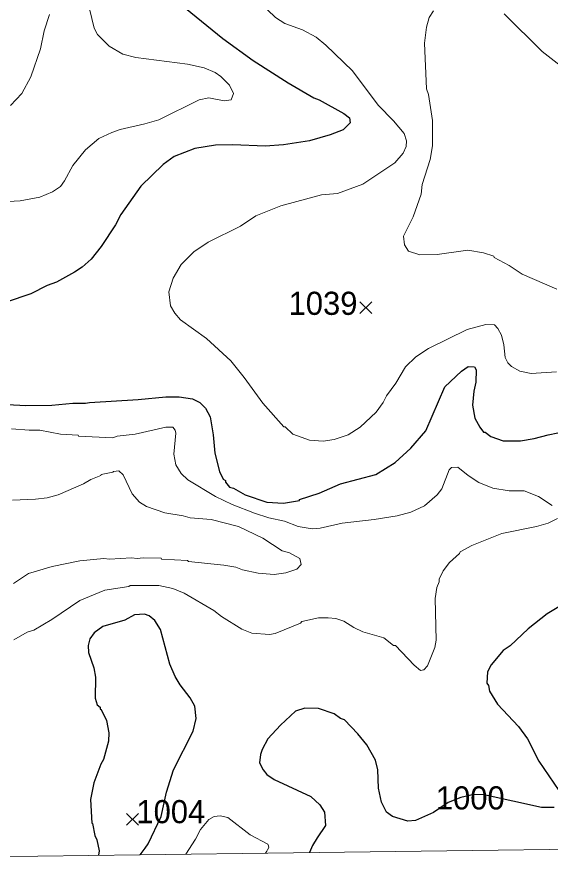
# Model space of a CAD drawing. Extents: x 265.7 to 292.1, y 7676.2 to 7704.2.
# Drawn here: x 285.312 to 287.156, y 7676.365 to 7679.337 of the extents above; entities that cross this region are included whole.
import ezdxf
from ezdxf.enums import TextEntityAlignment as Align

# ---------------------------------------------------------------- set-up
doc = ezdxf.new("R2010")
doc.units = 0
doc.header["$LTSCALE"] = 0.032
for name, color, linetype, lineweight in [('1', 7, 'Continuous', 25), ('2', 7, 'Continuous', 13), ('21', 7, 'Continuous', 25), ('63', 7, 'Continuous', 25)]:
    doc.layers.add(name, color=color, linetype=linetype, lineweight=lineweight)
doc.layers.add('61', color=7, linetype='Continuous')

msp = doc.modelspace()

# ---------------------------------------------------------------- linework, layer by layer
at = {"layer": '1'}
for points in [[(285.8746, 7679.3833), (286.0222, 7679.2636), (286.1267, 7679.1878), (286.248, 7679.1104), (286.3366, 7679.0585), (286.355, 7679.0513), (286.4411, 7679.0042), (286.4603, 7678.9891), (286.4627, 7678.9715), (286.4387, 7678.9476), (286.3933, 7678.93), (286.3214, 7678.9093), (286.2321, 7678.8957), (286.1682, 7678.8909), (286.0565, 7678.8957), (285.9975, 7678.8949), (285.9257, 7678.883), (285.8538, 7678.855), (285.8163, 7678.8279), (285.7389, 7678.7529), (285.6703, 7678.6548), (285.6511, 7678.6196), (285.6017, 7678.5438), (285.5674, 7678.4999), (285.5362, 7678.4728), (285.5099, 7678.4552), (285.4469, 7678.4209), (285.415, 7678.409), (285.3591, 7678.381), (285.2729, 7678.3523)], [(285.8251, 7678.0244), (285.8714, 7678.0244), (285.9177, 7678.0172), (285.9432, 7678.0052), (285.9624, 7677.9853), (285.9783, 7677.9557), (285.9887, 7677.8935), (285.9943, 7677.8297), (286.011, 7677.7658), (286.0238, 7677.7395), (286.031, 7677.7347), (286.031, 7677.7299), (286.0454, 7677.7123), (286.0597, 7677.7084), (286.0996, 7677.6852), (286.1746, 7677.6597), (286.2321, 7677.6565), (286.2879, 7677.6661), (286.2879, 7677.6693), (286.355, 7677.6916), (286.4292, 7677.7235), (286.5513, 7677.7554), (286.6183, 7677.7969), (286.6725, 7677.8472), (286.7236, 7677.9071), (286.7898, 7678.0595), (286.8473, 7678.1129), (286.8704, 7678.1289), (286.892, 7678.1281), (286.8976, 7678.1177), (286.8968, 7678.0754), (286.8896, 7678.0435), (286.8848, 7677.9956), (286.8936, 7677.951), (286.9103, 7677.919), (286.9231, 7677.9023), (286.9287, 7677.9023), (286.9486, 7677.8871), (286.9917, 7677.8719), (287.0508, 7677.8727), (287.0987, 7677.8799), (287.1465, 7677.8935), (287.2471, 7677.9142)], [(285.3415, 7677.9948), (285.4309, 7677.9956), (285.5043, 7678.002), (285.5474, 7678.002), (285.5618, 7678.0052), (285.7294, 7678.0148), (285.8251, 7678.0244)], [(285.2346, 7678.0004), (285.3415, 7677.9948)], [(287.2567, 7677.3421), (287.1433, 7677.2743), (287.0779, 7677.2224), (287.0149, 7677.1634), (286.9917, 7677.1474), (286.9494, 7677.0979), (286.9375, 7677.0732), (286.9351, 7677.0349), (286.9406, 7677.0261), (286.9446, 7677.007), (286.9718, 7676.9615), (287.0444, 7676.8849), (287.0755, 7676.8418), (287.1146, 7676.7652), (287.184, 7676.663)], [(285.7368, 7676.441), (285.7541, 7676.4638), (285.7644, 7676.4793), (285.8092, 7676.5737), (285.8275, 7676.6574), (285.8522, 7676.7349), (285.9201, 7676.8689), (285.9296, 7676.912), (285.9256, 7676.9551), (285.9097, 7676.9838), (285.8754, 7677.0285), (285.8578, 7677.0572), (285.8395, 7677.1003), (285.8067, 7677.22), (285.7868, 7677.2511), (285.7676, 7677.2671), (285.7517, 7677.2735), (285.7166, 7677.2711), (285.6831, 7677.2527), (285.6081, 7677.2304), (285.5777, 7677.2088), (285.5626, 7677.1881), (285.557, 7677.1642), (285.5578, 7677.1402), (285.5769, 7677.0876), (285.5825, 7677.0556), (285.5809, 7676.9822), (285.5881, 7676.9599), (285.5985, 7676.9511), (285.5985, 7676.9447), (285.6017, 7676.9431), (285.62, 7676.9056), (285.6288, 7676.8625), (285.6272, 7676.8338), (285.6097, 7676.77), (285.6009, 7676.754), (285.5769, 7676.6902), (285.565, 7676.6327), (285.569, 7676.5505), (285.5714, 7676.5497), (285.5801, 7676.5082), (285.5873, 7676.4923), (285.5953, 7676.4548), (285.5923, 7676.4394)], [(286.588, 7676.5888), (286.5712, 7676.6231), (286.5608, 7676.671), (286.5576, 7676.7349), (286.5497, 7676.7684), (286.5201, 7676.821), (286.489, 7676.8593), (286.4427, 7676.908), (286.4292, 7676.9128), (286.4068, 7676.928), (286.3534, 7676.9463), (286.3055, 7676.9479), (286.2736, 7676.9375), (286.2217, 7676.8889), (286.1778, 7676.8418), (286.1578, 7676.8051), (286.1523, 7676.7875), (286.1491, 7676.7588), (286.1618, 7676.7349), (286.1746, 7676.7189), (286.1994, 7676.7013), (286.3262, 7676.6423), (286.3581, 7676.6136), (286.3733, 7676.5888), (286.3773, 7676.5425), (286.3486, 7676.4992), (286.3318, 7676.4733), (286.3219, 7676.4485)], [(286.845, 7676.6386), (286.8017, 7676.6216), (286.7508, 7676.5877), (286.6877, 7676.5601), (286.6614, 7676.5577), (286.6087, 7676.5729), (286.588, 7676.5888)], [(287.1673, 7676.604), (287.1242, 7676.6048), (286.9261, 7676.648), (286.8903, 7676.6499), (286.845, 7676.6386)]]:
    msp.add_lwpolyline(points, dxfattribs=at)
at = {"layer": '2'}
for points in [[(285.553, 7679.4001), (285.5777, 7679.2995), (285.5889, 7679.2772), (285.6296, 7679.2373)], [(286.5768, 7678.0052), (286.5521, 7677.9717), (286.497, 7677.919), (286.4555, 7677.8927), (286.4076, 7677.8767), (286.3693, 7677.8711), (286.3214, 7677.8751), (286.264, 7677.8951), (286.2377, 7677.9206), (286.2337, 7677.9206), (286.1602, 7678.002), (286.0964, 7678.0914), (286.0501, 7678.1488), (285.9655, 7678.2262), (285.8762, 7678.2901), (285.8562, 7678.3132), (285.8411, 7678.3396), (285.8355, 7678.3874), (285.8506, 7678.4345), (285.8778, 7678.4824), (285.9217, 7678.5263), (285.9719, 7678.559), (286.0837, 7678.6141), (286.1363, 7678.65), (286.2225, 7678.6851), (286.3629, 7678.7226), (286.4188, 7678.7274), (286.5066, 7678.7601), (286.6167, 7678.8335), (286.6454, 7678.867), (286.6558, 7678.8894), (286.6574, 7678.9093), (286.6486, 7678.9348), (286.6127, 7678.9787), (286.5592, 7679.033), (286.4707, 7679.1511), (286.3789, 7679.2405), (286.3454, 7679.2676), (286.2975, 7679.2931), (286.2369, 7679.3155), (286.2041, 7679.3362), (286.1499, 7679.3873)], [(285.2881, 7679.0314), (285.328, 7679.0729), (285.3591, 7679.1303), (285.3918, 7679.2277), (285.4046, 7679.2899), (285.4229, 7679.3458)], [(286.7499, 7679.3594), (286.7356, 7679.3362), (286.726, 7679.3027), (286.7196, 7679.2468), (286.7268, 7679.0888), (286.7332, 7679.0697), (286.7468, 7678.9803), (286.7468, 7678.8925), (286.7388, 7678.8447), (286.7108, 7678.7585), (286.7077, 7678.725), (286.6805, 7678.6468), (286.647, 7678.5797), (286.6502, 7678.5502), (286.6638, 7678.5279), (286.7029, 7678.5151), (286.7635, 7678.5167), (286.8688, 7678.5319), (286.9231, 7678.5223), (286.959, 7678.5103), (286.9606, 7678.5063), (287.0125, 7678.4784), (287.0572, 7678.4489), (287.1769, 7678.3962)], [(287.1992, 7679.1623), (287.1266, 7679.2189), (286.9949, 7679.3482)], [(285.6296, 7679.2373), (285.6767, 7679.2093), (285.7214, 7679.1974), (285.9001, 7679.1742), (285.9576, 7679.1615), (285.9959, 7679.1463), (286.015, 7679.1319)], [(286.015, 7679.1319), (286.0453, 7679.1016), (286.0589, 7679.0729), (286.0509, 7679.0513), (286.027, 7679.0473), (285.9735, 7679.0585), (285.94, 7679.0513), (285.8012, 7678.9827), (285.7533, 7678.9683), (285.6671, 7678.9484), (285.6384, 7678.9388), (285.5937, 7678.9181), (285.5474, 7678.879), (285.5035, 7678.8239), (285.4756, 7678.7713), (285.4612, 7678.7521), (285.4341, 7678.7329), (285.3894, 7678.7146), (285.3224, 7678.7018), (285.2609, 7678.6986)], [(287.1753, 7678.1113), (287.0875, 7678.105), (287.0492, 7678.1137), (287.0205, 7678.1289), (287.0077, 7678.1417), (286.9981, 7678.1608), (286.9941, 7678.2047), (286.9853, 7678.2382), (286.9726, 7678.2606), (286.9614, 7678.2733), (286.9311, 7678.2749), (286.8673, 7678.2574)], [(286.8673, 7678.2574), (286.7332, 7678.1919), (286.6893, 7678.1632), (286.6534, 7678.1281), (286.6199, 7678.0722), (286.588, 7678.0276), (286.5768, 7678.0052)], [(285.2921, 7677.9142), (285.3527, 7677.9087), (285.3902, 7677.9087), (285.4612, 7677.8959), (285.5219, 7677.8919), (285.5235, 7677.8887), (285.6416, 7677.8823), (285.6567, 7677.8879), (285.7198, 7677.8951), (285.8251, 7677.9198), (285.8491, 7677.9198), (285.8578, 7677.9087), (285.8602, 7677.8983), (285.853, 7677.8265), (285.8602, 7677.7898), (285.8786, 7677.7594), (285.9017, 7677.7371), (285.9975, 7677.6796), (286.0549, 7677.6525), (286.1315, 7677.6222), (286.1818, 7677.6062), (286.2353, 7677.5951), (286.2831, 7677.5759), (286.331, 7677.5679), (286.3582, 7677.5703), (286.4348, 7677.5879), (286.5449, 7677.5998), (286.6247, 7677.6126), (286.6725, 7677.6262), (286.7188, 7677.6477), (286.7635, 7677.6852), (286.7795, 7677.706), (286.805, 7677.7722), (286.813, 7677.7802), (286.8345, 7677.7818), (286.8704, 7677.7523), (286.9071, 7677.7283), (286.955, 7677.7084), (287.0125, 7677.6996), (287.0635, 7677.6996), (287.113, 7677.6796), (287.1609, 7677.6485)], [(285.2985, 7677.3788), (285.3503, 7677.4139), (285.4325, 7677.4379), (285.5283, 7677.457), (285.6113, 7677.465), (285.6304, 7677.4634), (285.707, 7677.4674), (285.7262, 7677.465), (285.7469, 7677.4682), (285.8092, 7677.4666), (285.8108, 7677.4634), (285.9001, 7677.4586), (285.9033, 7677.4554), (286.0262, 7677.4426), (286.0677, 7677.4355), (286.09, 7677.4259), (286.1443, 7677.4147), (286.2002, 7677.4099), (286.2401, 7677.4155), (286.2776, 7677.4283), (286.2927, 7677.445), (286.2887, 7677.4658), (286.2528, 7677.4849), (286.2273, 7677.4921), (286.1603, 7677.536), (286.0765, 7677.5759), (285.9815, 7677.6006), (285.9097, 7677.6062), (285.8858, 7677.6134), (285.8219, 7677.623), (285.7581, 7677.6453), (285.7341, 7677.6605), (285.7094, 7677.6892), (285.6775, 7677.7547), (285.6631, 7677.7682), (285.6448, 7677.7666), (285.6416, 7677.7634), (285.6017, 7677.7554), (285.6009, 7677.7523), (285.5666, 7677.7387), (285.5402, 7677.7235), (285.4533, 7677.6852), (285.415, 7677.6757), (285.3751, 7677.6709), (285.2953, 7677.6677)], [(287.1792, 7677.6038), (287.1465, 7677.5871), (287.1066, 7677.5759), (286.9869, 7677.552), (286.8832, 7677.5105)], [(286.8832, 7677.5105), (286.8425, 7677.4881), (286.8401, 7677.4825), (286.8058, 7677.4514), (286.7843, 7677.4227), (286.7699, 7677.394), (286.7699, 7677.3852)], [(286.7699, 7677.3852), (286.7619, 7677.3653), (286.7563, 7677.3269), (286.7595, 7677.1833), (286.7555, 7677.1578), (286.73, 7677.0939), (286.7172, 7677.0804), (286.7061, 7677.078), (286.6837, 7677.0963), (286.6191, 7677.1642), (286.6127, 7677.165), (286.5784, 7677.1913), (286.5066, 7677.212), (286.4747, 7677.2264), (286.4411, 7677.2487), (286.4124, 7677.2575), (286.3869, 7677.2607), (286.3534, 7677.2599), (286.2959, 7677.2479), (286.2903, 7677.2424), (286.2033, 7677.2064), (286.1842, 7677.2025), (286.1227, 7677.2072), (286.0884, 7677.2216), (286.0174, 7677.2647), (285.9911, 7677.2854), (285.889, 7677.3461), (285.8491, 7677.3613), (285.8012, 7677.3724), (285.7022, 7677.3724), (285.6974, 7677.3692), (285.6145, 7677.3565), (285.5283, 7677.3206), (285.4309, 7677.2551), (285.3687, 7677.2176), (285.3463, 7677.2112), (285.3001, 7677.1841)], [(285.8942, 7676.4432), (285.928, 7676.4955), (285.9456, 7676.529), (285.9743, 7676.5625), (285.9927, 7676.5737), (286.0134, 7676.5753), (286.0398, 7676.5705), (286.1172, 7676.5098), (286.1778, 7676.4779), (286.1805, 7676.4719), (286.181, 7676.4667), (286.177, 7676.458), (286.1744, 7676.4531), (286.1701, 7676.4465)]]:
    msp.add_lwpolyline(points, dxfattribs=at)
at = {"layer": '21'}
for p, q in [((286.4957, 7678.3532), (286.5369, 7678.312)), ((286.5369, 7678.3532), (286.4957, 7678.312)), ((285.6893, 7676.5842), (285.7305, 7676.543)), ((285.7305, 7676.5842), (285.6893, 7676.543))]:
    msp.add_line(p, q, dxfattribs=at)
at = {"layer": '63', "lineweight": 13}
msp.add_lwpolyline([(292.1022, 7676.5221), (291.5717, 7676.5154), (291.0411, 7676.5087), (290.5106, 7676.5021), (289.9801, 7676.4954), (289.4496, 7676.4887), (288.9191, 7676.4819), (288.3886, 7676.4752), (287.858, 7676.4684), (287.3275, 7676.4616), (286.797, 7676.4548), (286.2665, 7676.448), (285.7359, 7676.4412), (285.2054, 7676.4343), (284.6749, 7676.4275), (284.1443, 7676.4206), (283.6138, 7676.4137), (283.0833, 7676.4067), (282.5527, 7676.3998), (282.0222, 7676.3929), (281.4917, 7676.3859), (280.9611, 7676.3789), (280.4306, 7676.3719), (279.9, 7676.3649)], dxfattribs=at)

# ---------------------------------------------------------------- texts
at = {"layer": '61'}
for s, p in [('1039', (286.3686, 7678.3078)), ('1000', (286.8775, 7676.5978)), ('1004', (285.8426, 7676.5502))]:
    msp.add_text(s, height=0.08, dxfattribs=at).set_placement(p, align=Align.CENTER)

doc.saveas('drawing.dxf')
